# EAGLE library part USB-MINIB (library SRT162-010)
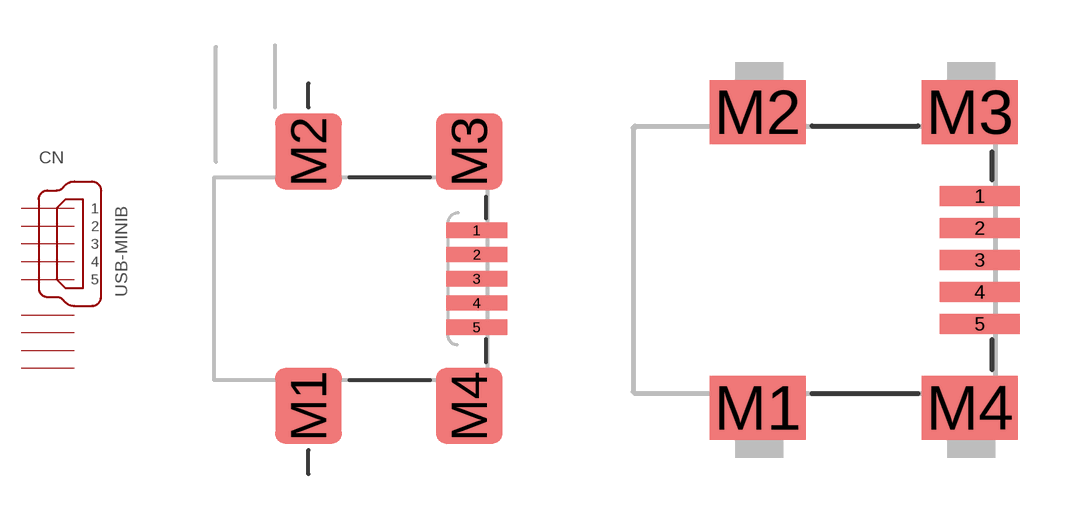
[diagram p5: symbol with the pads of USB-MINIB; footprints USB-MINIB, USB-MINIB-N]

Designator prefix CN

## USB-MINIB  [USB-MINIB]
1  1  in
2  2  in
3  3  in
4  4  in
5  5  in
M1  GND  pwr
M2  GND  pwr
M3  GND  pwr
M4  GND  pwr

## USB-MINIBN  [USB-MINIB-N]
Pads as for USB-MINIB

## USB-MINIBTH  [USB-MINIB-TH]
Pads as for USB-MINIB

## Footprint USB-MINIB (pad centres in mm)
HIROSE UX60A-MB-5ST
smd 2 x 0.5: 1 2.25,1.6; 2 2.25,0.8; 3 2.25,0; 4 2.25,-0.8; 5 2.25,-1.6
smd 2.2 x 2.5: M1 -3.3,-4.2; M2 -3.3,4.2; M3 2,4.2; M4 2,-4.2

## Footprint USB-MINIB-N (pad centres in mm)
smd 2 x 0.5: 1 3.52,1.6; 2 3.52,0.8; 3 3.52,0; 4 3.52,-0.8; 5 3.52,-1.6
smd 2.4 x 1.6: M1 -2.03,-3.7; M2 -2.03,3.7; M3 3.27,3.7; M4 3.27,-3.7

## Footprint USB-MINIB-TH (pad centres in mm)
drill 0.7 pad 1.1 round: 1 0.705,-1.6; 2 -1.045,-0.8; 3 0.705,0; 4 -1.045,0.8; 5 0.705,1.6
drill 1 long: M1 -0.145,3.7; M2 -0.145,-3.7; M3 4.65,-3.7; M4 4.65,3.7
